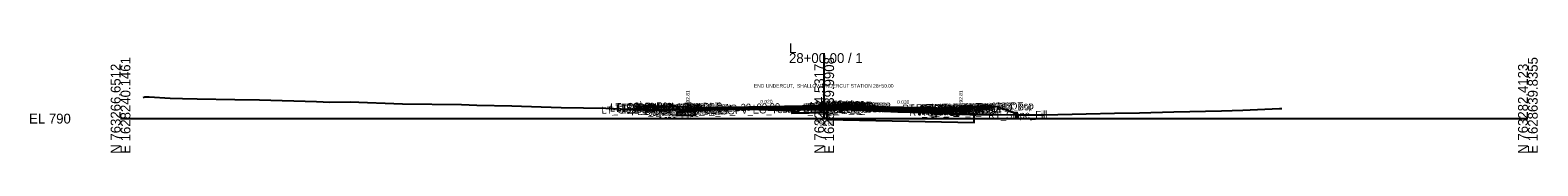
# Model space of a CAD drawing. Extents: x -26 to 4403, y -510 to 9556.
# Drawn here: x 974.3 to 1402.8, y 7990.3 to 8021.4 of the extents above; entities that cross this region are included whole.
import ezdxf

# ---------------------------------------------------------------- set-up
doc = ezdxf.new("R2010")
doc.units = 0
for name, color, linetype in [('Default', 7, 'Continuous'), ('Exist CMT Pavement', 7, 'Continuous'), ('Exist Cross Section Cell', 7, 'Continuous'), ('Exist XS Center Line Elevation Label', 7, 'Continuous'), ('Exist XS Ground Line', 7, 'Continuous'), ('Prop CMT Conc Surface', 7, 'Continuous'), ('Prop CMT Concrete Structures', 7, 'Continuous'), ('Prop CMT Pvmt Course 1', 7, 'Continuous'), ('Prop CMT Pvmt Course 1 CG', 7, 'Continuous'), ('Prop CMT Pvmt Course 1 Wedge', 7, 'Continuous'), ('Prop CMT Pvmt Course 2', 7, 'Continuous'), ('Prop CMT Pvmt Course 2 Wedge', 7, 'Continuous'), ('Prop CMT Pvmt Course 3', 7, 'Continuous'), ('Prop CMT Pvmt Course 3 Wedge', 7, 'Continuous'), ('Prop CMT Pvmt Surface', 7, 'Continuous'), ('Prop CMT Pvmt Wedge Surface 1', 7, 'Continuous'), ('Prop CMT Pvmt Wedge Surface 2', 7, 'Continuous'), ('Prop CMT Pvmt Wedge Surface 3', 7, 'Continuous'), ('Prop CMT Shallow Undercut', 7, 'Continuous'), ('Prop CMT Shallow Undercut Boundary', 7, 'Continuous'), ('Prop CMT Slope Grass', 7, 'Continuous'), ('Prop CMT Subgrade Earthwork', 7, 'Continuous'), ('Prop CMT Undercut Boundary', 7, 'Continuous'), ('Prop XS Finish Grade CurbGutter', 7, 'Continuous'), ('Prop XS Hydro Elevations', 7, 'Continuous'), ('Prop XS SE Text', 7, 'Continuous'), ('Prop XS Side Slope Text', 7, 'Continuous'), ('Prop XSC Text', 7, 'Continuous'), ('Scratch_Level_0', 7, 'Continuous')]:
    doc.layers.add(name, color=color, linetype=linetype)

msp = doc.modelspace()

# ---------------------------------------------------------------- linework, layer by layer
at = {"layer": 'Exist CMT Pavement'}
msp.add_lwpolyline([(1163.26, 8002.76), (1166.71, 8002.81), (1171.43, 8002.87), (1181.81, 8002.55), (1190.76, 8002.26)], dxfattribs=at)
at = {"layer": 'Exist Cross Section Cell'}
for p, q in [((1200, 8000), (1200, 8018.61)), ((1000, 8000), (1200, 8000)), ((1200, 8000), (1400, 8000))]:
    msp.add_line(p, q, dxfattribs=at)
at = {"layer": 'Exist XS Ground Line'}
msp.add_lwpolyline([(1006.41, 8006.02), (1006.94, 8006.2), (1008.09, 8006.2), (1014.15, 8005.86), (1017.63, 8005.71), (1021.77, 8005.64), (1032.52, 8005.47), (1039.51, 8005.33), (1055.67, 8004.87), (1059.53, 8004.72), (1065.22, 8004.76), (1080.13, 8004.17), (1096.91, 8004), (1101.24, 8003.86), (1111.18, 8003.65), (1119.56, 8003.38), (1125.27, 8003.17), (1137.91, 8002.99), (1144.49, 8002.66), (1149.13, 8002.46), (1149.67, 8002.18), (1155.82, 8002.47), (1161.33, 8002.74), (1166.71, 8002.81), (1171.43, 8002.87), (1181.81, 8002.55), (1190.76, 8002.26), (1191.82, 8002.14), (1192.49, 8002.07), (1193.16, 8002.52), (1196.15, 8002.55), (1200.28, 8002.62), (1206.77, 8002.58), (1207.39, 8002.57), (1208.7, 8002.51), (1220.89, 8001.89), (1227.96, 8001.76), (1236.63, 8001.33), (1242.45, 8001.17), (1254.46, 8001.1), (1262.38, 8001.04), (1274.45, 8001.34), (1282.53, 8001.52), (1289.58, 8001.62), (1299.42, 8001.95), (1312.95, 8002.23), (1318.95, 8002.43), (1329.38, 8002.85), (1330.09, 8002.88)], dxfattribs=at)
at = {"layer": 'Prop CMT Conc Surface'}
for points in [[(1154.57, 8003.44), (1149.57, 8003.54)], [(1154.57, 8003.44), (1154.57, 8003.44)], [(1161.25, 8002.81), (1161.25, 8003.31), (1160.75, 8003.31)], [(1163.25, 8002.93), (1161.25, 8002.81)], [(1236.89, 8002.93), (1238.89, 8002.81)], [(1238.89, 8002.81), (1238.89, 8003.31), (1239.39, 8003.31)], [(1243.4, 8003.4), (1248.4, 8003.5)]]:
    msp.add_lwpolyline(points, dxfattribs=at)
at = {"layer": 'Prop CMT Concrete Structures'}
for points in [[(1149.57, 8003.21), (1149.57, 8003.54)], [(1149.57, 8003.54), (1154.57, 8003.44)], [(1154.57, 8003.11), (1149.57, 8003.21)], [(1154.57, 8003.44), (1154.57, 8003.44)], [(1163.25, 8002.93), (1161.25, 8002.81), (1161.25, 8003.31), (1160.75, 8003.31)], [(1160.75, 8003.31), (1160.75, 8002.29), (1163.25, 8002.35)], [(1163.25, 8002.35), (1163.25, 8002.93)], [(1208, 8003.5), (1207.99, 8003.67), (1207.24, 8003.92), (1206, 8004.18), (1204.76, 8004.16), (1204.01, 8003.91), (1204, 8003.74)], [(1204, 8003.74), (1208, 8003.5)], [(1236.89, 8002.93), (1238.89, 8002.81), (1238.89, 8003.31), (1239.39, 8003.31)], [(1239.39, 8003.31), (1239.39, 8002.29), (1236.89, 8002.34)], [(1236.89, 8002.34), (1236.89, 8002.93)], [(1248.4, 8003.5), (1243.4, 8003.4)], [(1243.4, 8003.4), (1243.4, 8003.06)], [(1243.4, 8003.06), (1248.4, 8003.16)], [(1248.4, 8003.16), (1248.4, 8003.5)]]:
    msp.add_lwpolyline(points, dxfattribs=at)
msp.add_lwpolyline([(1154.57, 8003.44), (1154.57, 8003.11), (1154.57, 8003.11)], close=True, dxfattribs=at)
at = {"layer": 'Prop CMT Pvmt Course 1'}
for points in [[(1204, 8003.74), (1163.25, 8002.93)], [(1163.25, 8002.8), (1204, 8003.62)], [(1163.25, 8002.93), (1163.25, 8002.68), (1163.25, 8002.68), (1163.25, 8002.8)], [(1204, 8003.74), (1208, 8003.5)], [(1204, 8003.49), (1204, 8003.74)], [(1204, 8003.49), (1204, 8003.74)], [(1204, 8003.62), (1204, 8003.49), (1204, 8003.49)], [(1208, 8003.25), (1204, 8003.49)], [(1208, 8003.5), (1208, 8003.25)], [(1208, 8003.5), (1236.89, 8002.93)], [(1208, 8003.25), (1208, 8003.5)], [(1236.89, 8002.68), (1208, 8003.25)], [(1236.89, 8002.93), (1236.89, 8002.68)]]:
    msp.add_lwpolyline(points, dxfattribs=at)
msp.add_lwpolyline([(1208, 8003.25), (1208, 8003.38), (1208, 8003.38), (1208, 8003.25)], close=True, dxfattribs=at)
at = {"layer": 'Prop CMT Pvmt Course 1 CG'}
for points in [[(1163.25, 8002.35), (1160.25, 8002.28), (1159.91, 8001.94)], [(1159.91, 8001.94), (1163.25, 8002.01)], [(1163.25, 8002.01), (1163.25, 8002.35)], [(1236.89, 8002.34), (1239.89, 8002.28), (1240.23, 8001.94)], [(1236.89, 8002.01), (1236.89, 8002.34)], [(1240.23, 8001.94), (1236.89, 8002.01)]]:
    msp.add_lwpolyline(points, dxfattribs=at)
at = {"layer": 'Prop CMT Pvmt Course 1 Wedge'}
for points in [[(1163.25, 8002.8), (1166.71, 8002.87), (1171.43, 8002.97), (1181.81, 8003.17), (1190.76, 8003.35), (1191.82, 8003.37), (1192.49, 8003.39), (1192.87, 8003.4), (1193.16, 8003.4), (1196.15, 8003.46), (1200.28, 8003.54), (1204, 8003.62)], [(1204, 8003.49), (1200.28, 8003.42), (1196.15, 8003.34), (1193.16, 8003.28), (1192.87, 8003.27), (1192.49, 8003.26), (1191.82, 8003.25), (1190.76, 8003.23), (1181.81, 8003.05), (1172.02, 8002.85), (1171.43, 8002.87), (1166.71, 8002.81), (1163.25, 8002.76)], [(1163.25, 8002.76), (1163.25, 8002.8)], [(1204, 8003.62), (1204, 8003.49)]]:
    msp.add_lwpolyline(points, dxfattribs=at)
at = {"layer": 'Prop CMT Pvmt Course 2'}
for points in [[(1163.25, 8002.35), (1163.25, 8002.35), (1163.25, 8002.68), (1163.25, 8002.68)], [(1163.25, 8002.68), (1163.25, 8002.35)], [(1204, 8003.49), (1208, 8003.25)], [(1204, 8003.16), (1204, 8003.49)], [(1208, 8002.92), (1204, 8003.16)], [(1208, 8003.25), (1208, 8002.92)], [(1208, 8002.92), (1208, 8003.25)], [(1208, 8003.25), (1236.89, 8002.68)], [(1236.89, 8002.34), (1208, 8002.92)], [(1236.89, 8002.68), (1236.89, 8002.34)]]:
    msp.add_lwpolyline(points, dxfattribs=at)
at = {"layer": 'Prop CMT Pvmt Course 2 Wedge'}
for points in [[(1204, 8003.16), (1200.28, 8003.09), (1196.15, 8003), (1193.16, 8002.94), (1192.87, 8002.94), (1192.49, 8002.93), (1191.82, 8002.92), (1190.76, 8002.89), (1181.81, 8002.72), (1178.53, 8002.65), (1172.02, 8002.85)], [(1172.02, 8002.85), (1181.81, 8003.05)], [(1181.81, 8003.05), (1190.76, 8003.23), (1191.82, 8003.25), (1192.49, 8003.26), (1192.87, 8003.27), (1193.16, 8003.28), (1196.15, 8003.34), (1200.28, 8003.42), (1204, 8003.49)], [(1204, 8003.49), (1204, 8003.16)]]:
    msp.add_lwpolyline(points, dxfattribs=at)
at = {"layer": 'Prop CMT Pvmt Course 3'}
for points in [[(1163.25, 8002.35), (1163.25, 8002.35), (1163.25, 8002.01), (1163.25, 8002.01)], [(1163.25, 8002.01), (1163.25, 8002.35)], [(1204, 8003.16), (1208, 8002.92)], [(1204, 8002.83), (1204, 8003.16)], [(1208, 8002.59), (1204, 8002.83)], [(1208, 8002.92), (1208, 8002.59)], [(1208, 8002.92), (1236.89, 8002.34)], [(1208, 8002.59), (1208, 8002.92)], [(1236.89, 8002.01), (1208, 8002.59)], [(1236.89, 8002.34), (1236.89, 8002.01)]]:
    msp.add_lwpolyline(points, dxfattribs=at)
at = {"layer": 'Prop CMT Pvmt Course 3 Wedge'}
for points in [[(1178.52, 8002.65), (1181.81, 8002.72)], [(1204, 8002.59), (1200.28, 8002.62), (1196.15, 8002.55), (1193.16, 8002.52), (1192.87, 8002.37), (1192.49, 8002.07), (1191.82, 8002.14), (1190.76, 8002.26), (1181.81, 8002.55), (1178.52, 8002.65)], [(1181.81, 8002.72), (1190.76, 8002.9), (1191.82, 8002.92), (1192.49, 8002.93), (1192.87, 8002.94), (1193.16, 8002.94), (1196.15, 8003), (1200.28, 8003.09), (1204, 8003.16)]]:
    msp.add_lwpolyline(points, dxfattribs=at)
at = {"layer": 'Prop CMT Pvmt Surface'}
for points in [[(1204, 8003.74), (1163.25, 8002.93)], [(1204, 8003.74), (1208, 8003.5)], [(1208, 8003.5), (1236.89, 8002.93)]]:
    msp.add_lwpolyline(points, dxfattribs=at)
at = {"layer": 'Prop CMT Pvmt Wedge Surface 1'}
for points in [[(1204, 8003.62), (1163.25, 8002.8)], [(1163.25, 8002.68), (1163.25, 8002.93)], [(1163.25, 8002.8), (1163.25, 8002.68), (1163.25, 8002.68)], [(1204, 8003.74), (1204, 8003.49), (1204, 8003.49), (1204, 8003.62)]]:
    msp.add_lwpolyline(points, dxfattribs=at)
at = {"layer": 'Prop CMT Pvmt Wedge Surface 2'}
for points in [[(1204, 8003.49), (1163.25, 8002.68)], [(1163.25, 8002.68), (1163.25, 8002.93)], [(1204, 8003.74), (1204, 8003.49)]]:
    msp.add_lwpolyline(points, dxfattribs=at)
at = {"layer": 'Prop CMT Pvmt Wedge Surface 3'}
for points in [[(1204, 8003.16), (1163.25, 8002.35)], [(1163.25, 8002.35), (1163.25, 8002.93)], [(1204, 8003.74), (1204, 8003.16)]]:
    msp.add_lwpolyline(points, dxfattribs=at)
at = {"layer": 'Prop CMT Shallow Undercut'}
for points in [[(1158.22, 8001.91), (1163.25, 8002.01), (1163.23, 8001.01), (1158.22, 8000.91)], [(1190.76, 8002.26), (1190.76, 8001.56), (1200.76, 8001.76), (1200.76, 8002.61), (1200.28, 8002.62), (1199.7, 8002.61), (1198.37, 8002.59), (1196.09, 8002.55), (1193.16, 8002.52), (1192.49, 8002.07)]]:
    msp.add_lwpolyline(points, close=True, dxfattribs=at)
at = {"layer": 'Prop CMT Shallow Undercut Boundary'}
msp.add_line((1201.34, 8001.77), (1190.78, 8001.56), dxfattribs=at)
for points in [[(1158.22, 8001.91), (1158.22, 8000.91), (1163.23, 8001.01), (1163.25, 8002.01)], [(1158.22, 8001.91), (1158.22, 8000.91), (1163.23, 8001.01), (1163.25, 8002.01)], [(1190.76, 8002.26), (1190.76, 8001.56), (1200.76, 8001.76), (1200.76, 8002.61), (1200.29, 8002.62), (1199.91, 8002.61), (1199.01, 8002.6), (1195.29, 8002.54), (1193.16, 8002.52), (1192.49, 8002.07)]]:
    msp.add_lwpolyline(points, close=True, dxfattribs=at)
at = {"layer": 'Prop CMT Slope Grass'}
for p, q in [((1248.4, 8003.49), (1248.92, 8003.5)), ((1248.92, 8003.5), (1254.33, 8001.59))]:
    msp.add_line(p, q, dxfattribs=at)
for points in [[(1160.75, 8003.31), (1149.05, 8003.54), (1146.18, 8002.59)], [(1239.39, 8003.31), (1248.4, 8003.49)], [(1254.33, 8001.59), (1254.33, 8000.1), (1255, 8000.1), (1255, 8001.09)]]:
    msp.add_lwpolyline(points, dxfattribs=at)
at = {"layer": 'Prop CMT Subgrade Earthwork'}
msp.add_line((1190.76, 8002.26), (1190.76, 8002.56), dxfattribs=at)
for points in [[(1163.25, 8002.01), (1159.91, 8001.94), (1158.5, 8003.35)], [(1163.25, 8002.01), (1163.26, 8002.76)], [(1163.25, 8002.01), (1163.25, 8002.01)], [(1204, 8002.83), (1190.76, 8002.56)], [(1204, 8002.83), (1208, 8002.59)], [(1208, 8002.59), (1236.89, 8002.01)], [(1236.89, 8002.01), (1240.23, 8001.94), (1241.64, 8003.35)]]:
    msp.add_lwpolyline(points, dxfattribs=at)
at = {"layer": 'Prop CMT Undercut Boundary'}
msp.add_lwpolyline([(1200.76, 8002.61), (1200.76, 7999.76), (1200.76, 7999.76), (1242.64, 7998.89), (1242.64, 8001.17), (1242.45, 8001.17), (1240.41, 8001.22), (1236.23, 8001.35), (1230.28, 8001.64), (1228.34, 8001.74), (1226.32, 8001.79), (1221.11, 8001.89), (1216.97, 8002.09), (1213.06, 8002.29), (1211.97, 8002.35), (1207.75, 8002.55), (1206.77, 8002.58), (1203.69, 8002.6), (1201.28, 8002.61), (1200.76, 8002.61), (1200.76, 8002.61), (1200.76, 8002.61), (1200.76, 8002.61), (1200.76, 8002.61), (1200.76, 8002.61), (1200.76, 8002.61), (1200.76, 8002.61)], close=True, dxfattribs=at)
at = {"layer": 'Prop XS Finish Grade CurbGutter'}
for p, q in [((1254.33, 8001.59), (1254.53, 8001.59)), ((1254.33, 8001.59), (1255, 8001.59)), ((1254.33, 8001.59), (1254.33, 8000.59)), ((1255, 8001.18), (1254.65, 8001.54)), ((1255, 8001.18), (1255, 8000.59)), ((1255, 8001.09), (1255, 8001.09)), ((1254.33, 8000.6), (1254.33, 8000.1)), ((1254.33, 8000.59), (1255, 8000.59)), ((1254.33, 8000.1), (1255, 8000.1)), ((1255, 8000.6), (1255, 8000.1))]:
    msp.add_line(p, q, dxfattribs=at)
msp.add_arc((1254.53, 8001.43), 0.166, 43.9997, 90, dxfattribs=at)

# ---------------------------------------------------------------- texts
at = {"layer": 'Default'}
msp.add_text('-', height=0.0001, dxfattribs=at).set_placement((1000, 8000))
at = {"layer": 'Exist Cross Section Cell'}
for s, p in [('28+00.00 / 1', (1190, 8015.81)), ('L', (1190, 8018.61)), ('EL 790', (974, 7998.6))]:
    msp.add_text(s, height=2.8, dxfattribs=at).set_placement(p)
for s, p in [('N 763266.6512', (1000, 7990)), ('E 1628240.1461', (1002.8, 7990)), ('N 763274.5317', (1200, 7990)), ('E 1628439.9908', (1202.8, 7990)), ('N 763282.4123', (1400, 7990)), ('E 1628639.8355', (1402.8, 7990))]:
    msp.add_text(s, height=2.8, rotation=90, dxfattribs=at).set_placement(p)
at = {"layer": 'Exist XS Center Line Elevation Label'}
msp.add_text('792.61', height=1.2, dxfattribs=at).set_placement((1197.72, 7998.01))
at = {"layer": 'Prop XS Hydro Elevations'}
for p in [(1161.75, 8003.81), (1239.39, 8003.81)]:
    msp.add_text('792.81', height=1, rotation=90, dxfattribs=at).set_placement(p)
at = {"layer": 'Prop XS SE Text'}
for rotation, p in [(1.1457, (1181.86, 8004.3)), (358.8558, (1220.72, 8004.25))]:
    msp.add_text('0.020', height=1, rotation=rotation, dxfattribs=at).set_placement(p)
at = {"layer": 'Prop XS Side Slope Text'}
for s, rotation, p in [('3:1', 18.4276, (1146.63, 8003.53)), ('2.9:1', 340.6493, (1250.48, 8003.28))]:
    msp.add_text(s, height=1, rotation=rotation, dxfattribs=at).set_placement(p)
at = {"layer": 'Prop XSC Text'}
msp.add_text('END UNDERCUT,  SHALLOW UNDERCUT STATION 28+50.00', height=1, dxfattribs=at).set_placement((1180.07, 8008.81))
at = {"layer": 'Scratch_Level_0'}
for s, p in [('28+00.00', (1197.55, 8002.89)), ('MI_Top In', (1197.63, 8003.02)), ('MI_Top Out', (1198.49, 8002.74)), ('MI_Crown', (1199.09, 8003.05)), ('28+00.00', (1200.39, 8002.79)), ('LT_Slope_Fill', (1136.72, 8001.4)), ('LT_Sub_Trench_Out_DLT', (1139.09, 8001.96)), ('LT_CSLP_Pnt', (1139.24, 8002.35)), ('LT_SDWK_Out_Top', (1140.83, 8002.17)), ('LT_SDWK_Out_Bot', (1140.86, 8001.83)), ('LT_SDWK_In_Top', (1142.45, 8002.2)), ('LT_SDWK_In_Bot', (1142.49, 8001.87)), ('28+00.00', (1144.33, 8002.37)), ('LT_CG1_Shelf_Out', (1146.82, 8001.02)), ('LT_PV_Sub_Tie_Out', (1148.23, 8001.46)), ('LT_CG_Top_Face', (1148.53, 8002.05)), ('LT_CG_Top_BOC', (1149.05, 8002.07)), ('LT_CG_Bot_BOC', (1149.09, 8001.06)), ('LT_CG_Top_Gut', (1149.51, 8001.57)), ('LT_Sub_OEOP', (1150.04, 8000.75)), ('LT_Sub_OEOT_CG', (1150.64, 8000.76)), ('LT_PV_OEEOP_EG', (1150.82, 8001.51)), ('LT_Sub_OEEOP', (1152.48, 8000.8)), ('LT_PV2_OEEOP', (1152.58, 8001.46)), ('LT_PV3_OEEOP', (1152.58, 8001.13)), ('LT_PV1_OEEOP', (1153.15, 8001.6)), ('LT_CG_Bot_IE', (1153.19, 8001.14)), ('28+00.00', (1153.41, 8002.18)), ('LT_Sub_OEOT', (1153.35, 8000.81)), ('LT_PV2_OEOT', (1153.44, 8001.48)), ('LT_PV3_OEOT', (1153.44, 8001.15)), ('LT_PV1_OEOT', (1154.01, 8001.74)), ('28+00.00', (1154.15, 8002.17)), ('LT_PV_EG_TestPt', (1170.06, 8001.22)), ('28+00.00', (1176.28, 8002.19)), ('LT_PV_IEEOP_EG', (1192.21, 8001.36)), ('LT_PV2_IEEOP', (1193.98, 8002.29)), ('LT_PV3_IEEOP', (1193.98, 8001.96)), ('LT_PV1_IEEOP', (1194.54, 8002.43)), ('LT_PV2_PGL1', (1194.9, 8002.31)), ('LT_PV3_PGL1', (1194.9, 8001.98)), ('LT_PV2_PGL', (1195.23, 8002.32)), ('LT_PV3_PGL', (1195.23, 8001.98)), ('LT_PV4_PGL', (1195.23, 8001.65)), ('LT_PV1_PGL', (1195.8, 8002.58)), ('MI_Face In', (1195.92, 8002.75)), ('28+00.00', (1197.19, 8002.7)), ('RT_Sub_OEEOP', (1197.19, 8001.37)), ('RT_PV2_OEEOP', (1197.28, 8002.04)), ('RT_PV3_OEEOP', (1197.28, 8001.71)), ('RT_PV1_OEEOP', (1197.85, 8002.17)), ('RT_PV2_IEEOP', (1197.93, 8002.05)), ('MI_Face Out', (1198.28, 8002.48)), ('RT_PV1_IEEOP', (1198.49, 8002.19)), ('RT_PV2_PGL1', (1198.86, 8002.07)), ('RT_PV3_PGL1', (1198.86, 8001.74)), ('RT_PV2_PGL', (1199.19, 8002.08)), ('RT_PV4_PGL', (1199.19, 8001.41)), ('MI_Bot Out', (1199.28, 8002.33)), ('RT_PV1_PGL', (1199.75, 8002.34)), ('28+00.00', (1204.31, 8002.3)), ('RT_Sub_Trench_Out_DLT', (1222.18, 8001.96)), ('RT_Sub_OEOT_CG', (1224.24, 8000.76)), ('RT_CG_Top_Face', (1226.13, 8002.05)), ('RT_CG1_Shelf_Out', (1226.42, 8001.01)), ('RT_CG_Bot_IE', (1226.78, 8001.14)), ('RT_Sub_OEOT', (1226.94, 8000.81)), ('RT_PV2_OEOT', (1227.04, 8001.48)), ('RT_PV3_OEOT', (1227.04, 8001.14)), ('RT_CG_Top_Gut', (1227.1, 8001.57)), ('RT_PV1_OEOT', (1227.6, 8001.74)), ('RT_CG_Top_BOC', (1227.65, 8002.07)), ('RT_CG_Bot_BOC', (1227.68, 8001.06)), ('RT_Sub_OEOP', (1230.31, 8000.74)), ('RT_SDWK_In_Top', (1231.24, 8002.15)), ('RT_SDWK_In_Bot', (1231.27, 8001.82)), ('28+00.00', (1232.28, 8002.17)), ('28+00.00', (1233.25, 8002.18)), ('RT_SDWK_Out_Top', (1234.62, 8002.22)), ('RT_SDWK_Out_Bot', (1234.65, 8001.89)), ('28+00.00', (1236.42, 8002.26)), ('RT_Shld_O', (1240.96, 8002.34)), ('28+00.00', (1241.68, 8002.36)), ('CSLP_Pnt', (1241.8, 8002.35)), ('RT_Slope_Fill', (1246.64, 7999.89))]:
    msp.add_text(s, height=2, rotation=1.1458, dxfattribs=at).set_placement(p)

doc.saveas('drawing.dxf')
